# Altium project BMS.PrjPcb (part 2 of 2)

## Sheet USB protection.SchDoc
size A3; SheetNumber: 3; SheetTotal: 5
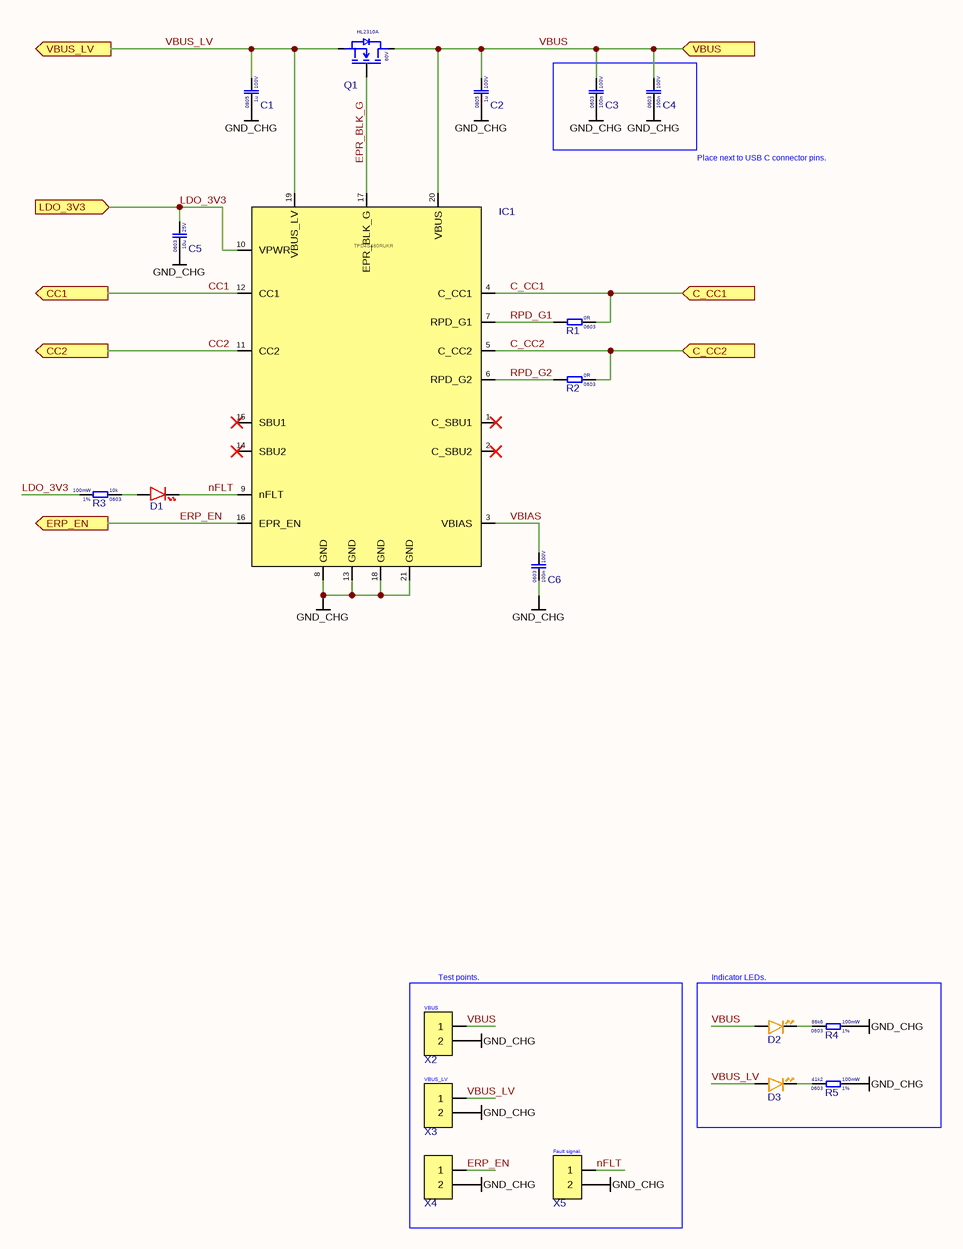
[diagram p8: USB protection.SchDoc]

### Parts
C1  Voltage Rating: 100V  Case Code (Imperial): 0805  Capacitance: 1u  [Cap_0805]  (hidden comment: CC0805KKX7R0BB105)
C2  Voltage Rating: 100V  Case Code (Imperial): 0805  Capacitance: 1u  [Cap_0805]  (hidden comment: CC0805KKX7R0BB105)
C3  Voltage Rating: 100V  Case Code (Imperial): 0603  Capacitance: 100n  [CAP 0603]  (hidden comment: CC0603KRX7R0BB104)
C4  Voltage Rating: 100V  Case Code (Imperial): 0603  Capacitance: 100n  [CAP 0603]  (hidden comment: CC0603KRX7R0BB104)
C5  Voltage Rating: 25V  Case Code (Imperial): 0603  Capacitance: 10u  [CAP 0603]  (hidden comment: CL10A106MA8NRNC)
C6  Voltage Rating: 100V  Case Code (Imperial): 0603  Capacitance: 100n  [CAP 0603]  (hidden comment: CC0603KRX7R0BB104)
D1  XL-1608SURC-06  [DIODE_0603_RED]  (value not drawn)
D2  XL-1608UOC-06  [DIODE_0603_ORANGE]  (value not drawn)
D3  XL-1608UOC-06  [DIODE_0603_ORANGE]  (value not drawn)
IC1  TPD4S480RUKR  [WQFN (20)]
Q1  Voltage: 60V  [SOT-23 GSD]  (hidden comment: HL2310A)
R1  Resistance: 0R  Case Code (Imperial): 0603  [RES_0603]  (hidden comment: 0603WAF0000T5E)
R2  Resistance: 0R  Case Code (Imperial): 0603  [RES_0603]  (hidden comment: 0603WAF0000T5E)
R3  Resistance Tolerance: 1%  Resistance: 10k  Power Rating: 100mW  Case Code (Imperial): 0603  [RES_0603]  (hidden comment: 0603WAF1002T5E)
R4  Resistance Tolerance: 1%  Resistance: 86k6  Power Rating: 100mW  Case Code (Imperial): 0603  [RES_0603]  (hidden comment: 0603WAF8662T5E)
R5  Resistance Tolerance: 1%  Resistance: 41k2  Power Rating: 100mW  Case Code (Imperial): 0603  [RES_0603]  (hidden comment: 0603WAF4122T5E)
X2  ZX-PZ1.27-1-2PZZ  [Pin header 1x2 1.27mmP THT Vertical]  (value not drawn)
X3  ZX-PZ1.27-1-2PZZ  [Pin header 1x2 1.27mmP THT Vertical]  (value not drawn)
X4  ZX-PZ1.27-1-2PZZ  [Pin header 1x2 1.27mmP THT Vertical]  (value not drawn)
X5  ZX-PZ1.27-1-2PZZ  [Pin header 1x2 1.27mmP THT Vertical]  (value not drawn)

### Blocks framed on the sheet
Test points.: X2-X5
Indicator LEDs.: D2 D3 R4 R5

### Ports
C_CC1 (in, see CHARGER[7B]), C_CC2 (in, see CHARGER[7B]), CC1 (out, see CHARGER[6B], USB PD[6C]), CC2 (out, see CHARGER[6B], USB PD[6C]), ERP_EN (out, see CHARGER[6B], USB PD[2B]), LDO_3V3 (in, see CHARGER[6C], USB PD[5C]), VBUS (in, see CHARGER[7B]), VBUS_LV (out, see CHARGER[6B], USB PD[6B])

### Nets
GND_CHG: C1.1 C2.1 C3.1 C4.1 C5.1 C6.1 IC1.8(GND) IC1.13(GND) IC1.18(GND) IC1.21(GND) R4.2 R5.2 X2.2 X3.2 X4.2 X5.2
LDO_3V3: C5.2 IC1.10(VPWR) R3.2 ; port LDO_3V3
C_CC1: IC1.4(C_CC1) R1.1 ; port C_CC1
C_CC2: IC1.5(C_CC2) R2.1 ; port C_CC2
CC1: IC1.12(CC1) ; port CC1
CC2: IC1.11(CC2) ; port CC2
EPR_BLK_G: IC1.17(EPR_BLK_G) Q1.G
ERP_EN: IC1.16(EPR_EN) X4.1 ; port ERP_EN
nFLT: D1.K IC1.9(nFLT) X5.1
RPD_G1: IC1.7(RPD_G1) R1.2
RPD_G2: IC1.6(RPD_G2) R2.2
VBIAS: C6.2 IC1.3(VBIAS)
VBUS: C2.2 C3.2 C4.2 D2.A IC1.20(VBUS) Q1.D X2.1 ; port VBUS
VBUS_LV: C1.2 D3.A IC1.19(VBUS_LV) Q1.S X3.1 ; port VBUS_LV
NetD1_A: D1.A R3.1
NetD2_K: D2.K R4.1
NetD3_K: D3.K R5.1

Not connected (* = marked no-connect by the designer): IC1 1(C_SBU1)* 2(C_SBU2)* 14(SBU2)* 15(SBU1)*

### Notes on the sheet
- Place next to USB C connector pins.
- (near X2) VBUS
- (near X3) VBUS_LV
- (near X5) Fault signal.

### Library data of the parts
C1 C2 = CC0805KKX7R0BB105: Cap 1uF 100V 0805 X7R; Manufacturer: Yageo
C3 C4 C6 = CC0603KRX7R0BB104: Cap 100nF 100V 0603 X7R; Manufacturer: YAGEO
C5 = CL10A106MA8NRNC: Cap 10uF 25V 0603 X5R; Manufacturer: Samsung
D1 = XL-1608SURC-06: LED Red 0603 25mA; Manufacturer: Xinglight
D2 D3 = XL-1608UOC-06: LED Orange 0603 20mA; Manufacturer: XINGLIGHT
IC1 = TPD4S480RUKR: USB PD protection IC; Manufacturer: Texas Instruments
Q1 = HL2310A: nMOS 60V 3A SOT-23; Manufacturer: hongjiacheng
R1 R2 = 0603WAF0000T5E: Res 0R 0603 1% 100mW 75V; Manufacturer: UNI-ROYAL
R3 = 0603WAF1002T5E: Res 10k 0603 1% 100mW 75V; Manufacturer: Uni-Royal
R4 = 0603WAF8662T5E: Res 86k6 0603 1% 100mW 75V; Manufacturer: Uni-Royal
R5 = 0603WAF4122T5E: Res 41k2 0603 1% 100mW 75V; Manufacturer: Uni-Royal
X2-X5 = ZX-PZ1.27-1-2PZZ: Pin header 1x2 1.27mmP THT Vertical; Manufacturer: Megastar

## Sheet USB PD.SchDoc
size A3; SheetNumber: 4; SheetTotal: 15
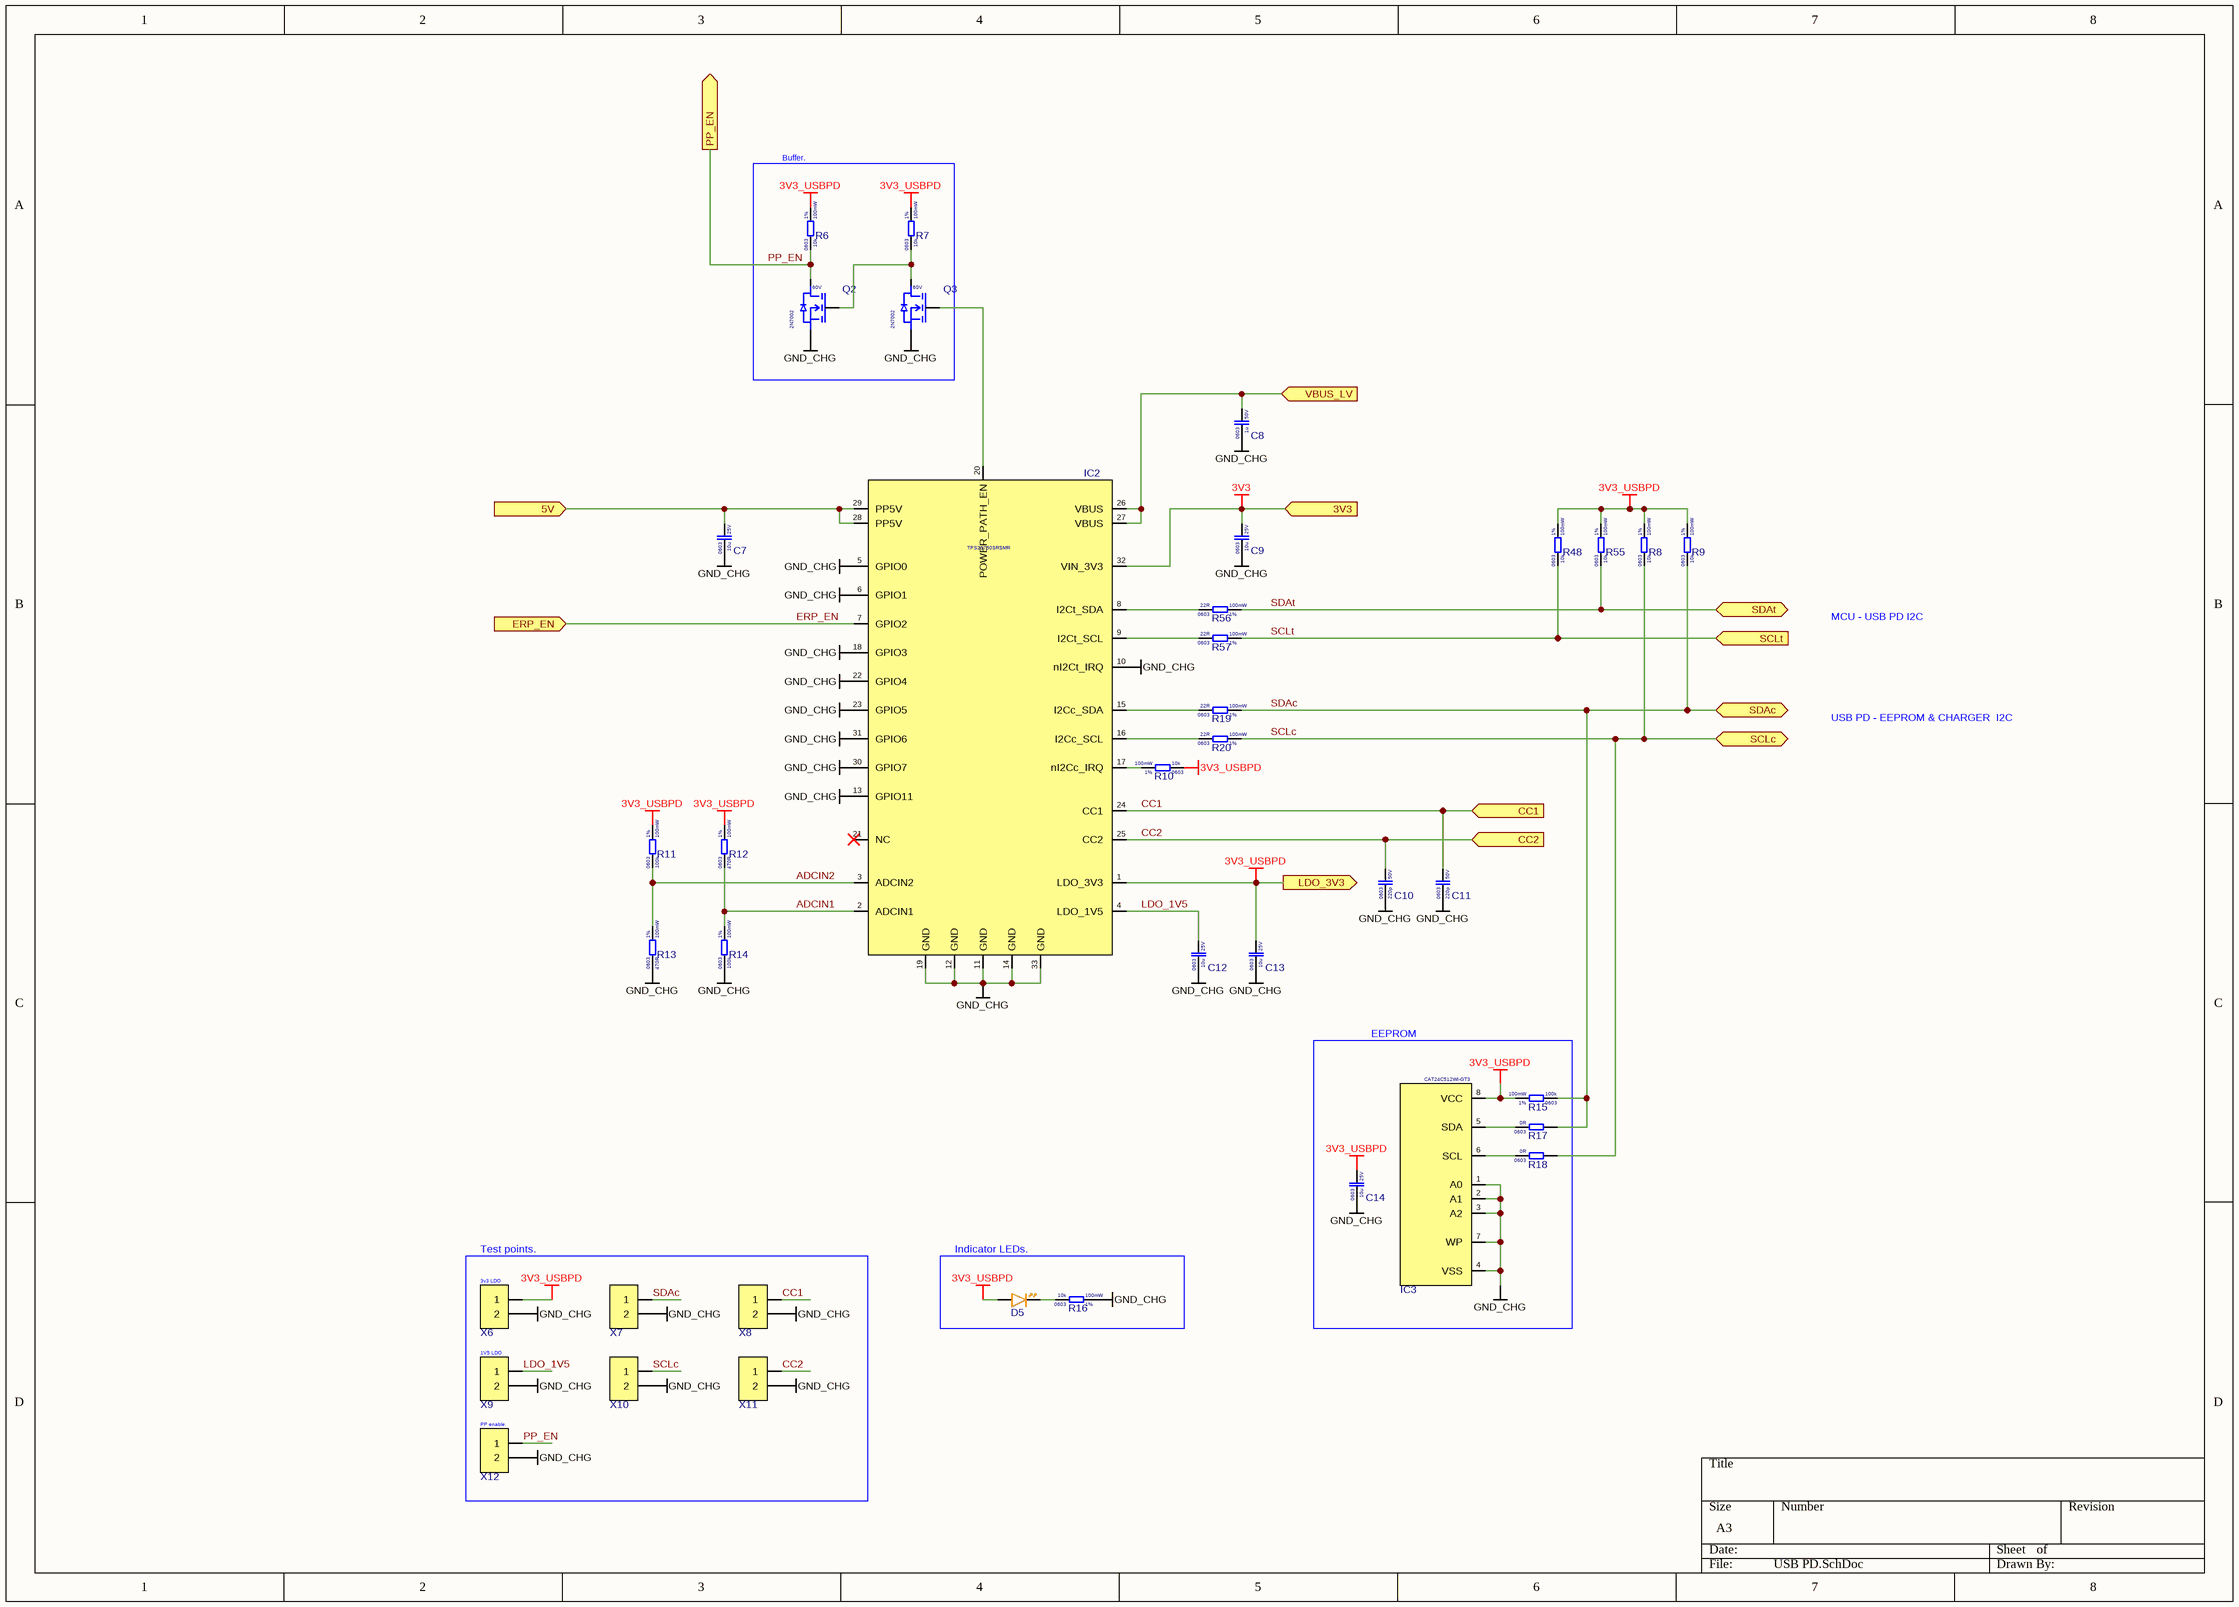
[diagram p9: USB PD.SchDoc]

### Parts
C7  Voltage Rating: 25V  Case Code (Imperial): 0603  Capacitance: 10u  [CAP 0603]  (hidden comment: CL10A106MA8NRNC)
C8  Voltage Rating: 50V  Case Code (Imperial): 0603  Capacitance: 1u  [CAP 0603]  (hidden comment: CL10A105KB8NNNC)
C9  Voltage Rating: 25V  Case Code (Imperial): 0603  Capacitance: 10u  [CAP 0603]  (hidden comment: CL10A106MA8NRNC)
C10  Voltage Rating: 50V  Case Code (Imperial): 0603  Capacitance: 220p  [CAP 0603]  (hidden comment: CL10B221KB8NNNC)
C11  Voltage Rating: 50V  Case Code (Imperial): 0603  Capacitance: 220p  [CAP 0603]  (hidden comment: CL10B221KB8NNNC)
C12  Voltage Rating: 25V  Case Code (Imperial): 0603  Capacitance: 10u  [CAP 0603]  (hidden comment: CL10A106MA8NRNC)
C13  Voltage Rating: 25V  Case Code (Imperial): 0603  Capacitance: 10u  [CAP 0603]  (hidden comment: CL10A106MA8NRNC)
C14  Voltage Rating: 25V  Case Code (Imperial): 0603  Capacitance: 10u  [CAP 0603]  (hidden comment: CL10A106MA8NRNC)
D5  XL-1608UOC-06  [DIODE_0603_ORANGE]  (value not drawn)
IC2  TPS26750SRSMR  [VQFN (32) 4x4]
IC3  CAT24C512WI-GT3  [SOIC8]
Q2  Voltage: 60V  [SOT-23 GSD]  (hidden comment: 2N7002)
Q3  Voltage: 60V  [SOT-23 GSD]  (hidden comment: 2N7002)
R6  Resistance Tolerance: 1%  Resistance: 10k  Power Rating: 100mW  Case Code (Imperial): 0603  [RES_0603]  (hidden comment: 0603WAF1002T5E)
R7  Resistance Tolerance: 1%  Resistance: 10k  Power Rating: 100mW  Case Code (Imperial): 0603  [RES_0603]  (hidden comment: 0603WAF1002T5E)
R8  Resistance Tolerance: 1%  Resistance: 10k  Power Rating: 100mW  Case Code (Imperial): 0603  [RES_0603]  (hidden comment: 0603WAF1002T5E)
R9  Resistance Tolerance: 1%  Resistance: 10k  Power Rating: 100mW  Case Code (Imperial): 0603  [RES_0603]  (hidden comment: 0603WAF1002T5E)
R10  Resistance Tolerance: 1%  Resistance: 10k  Power Rating: 100mW  Case Code (Imperial): 0603  [RES_0603]  (hidden comment: 0603WAF1002T5E)
R11  Resistance Tolerance: 1%  Resistance: 100k  Power Rating: 100mW  Case Code (Imperial): 0603  [RES_0603]  (hidden comment: 0603WAF1003T5E)
R12  Resistance Tolerance: 1%  Resistance: 470R  Power Rating: 100mW  Case Code (Imperial): 0603  [RES_0603]  (hidden comment: 0603WAF4700T5E)
R13  Resistance Tolerance: 1%  Resistance: 470R  Power Rating: 100mW  Case Code (Imperial): 0603  [RES_0603]  (hidden comment: 0603WAF4700T5E)
R14  Resistance Tolerance: 1%  Resistance: 100k  Power Rating: 100mW  Case Code (Imperial): 0603  [RES_0603]  (hidden comment: 0603WAF1003T5E)
R15  Resistance Tolerance: 1%  Resistance: 100k  Power Rating: 100mW  Case Code (Imperial): 0603  [RES_0603]  (hidden comment: 0603WAF1003T5E)
R16  Resistance Tolerance: 1%  Resistance: 10k  Power Rating: 100mW  Case Code (Imperial): 0603  [RES_0603]  (hidden comment: 0603WAF1002T5E)
R17  Resistance: 0R  Case Code (Imperial): 0603  [RES_0603]  (hidden comment: 0603WAF0000T5E)
R18  Resistance: 0R  Case Code (Imperial): 0603  [RES_0603]  (hidden comment: 0603WAF0000T5E)
R19  Resistance Tolerance: 1%  Resistance: 22R  Power Rating: 100mW  Case Code (Imperial): 0603  [RES_0603]  (hidden comment: 0603WAF220JT5E)
R20  Resistance Tolerance: 1%  Resistance: 22R  Power Rating: 100mW  Case Code (Imperial): 0603  [RES_0603]  (hidden comment: 0603WAF220JT5E)
R48  Resistance Tolerance: 1%  Resistance: 10k  Power Rating: 100mW  Case Code (Imperial): 0603  [RES_0603]  (hidden comment: 0603WAF1002T5E)
R55  Resistance Tolerance: 1%  Resistance: 10k  Power Rating: 100mW  Case Code (Imperial): 0603  [RES_0603]  (hidden comment: 0603WAF1002T5E)
R56  Resistance Tolerance: 1%  Resistance: 22R  Power Rating: 100mW  Case Code (Imperial): 0603  [RES_0603]  (hidden comment: 0603WAF220JT5E)
R57  Resistance Tolerance: 1%  Resistance: 22R  Power Rating: 100mW  Case Code (Imperial): 0603  [RES_0603]  (hidden comment: 0603WAF220JT5E)
X6  ZX-PZ1.27-1-2PZZ  [Pin header 1x2 1.27mmP THT Vertical]  (value not drawn)
X7  ZX-PZ1.27-1-2PZZ  [Pin header 1x2 1.27mmP THT Vertical]  (value not drawn)
X8  ZX-PZ1.27-1-2PZZ  [Pin header 1x2 1.27mmP THT Vertical]  (value not drawn)
X9  ZX-PZ1.27-1-2PZZ  [Pin header 1x2 1.27mmP THT Vertical]  (value not drawn)
X10  ZX-PZ1.27-1-2PZZ  [Pin header 1x2 1.27mmP THT Vertical]  (value not drawn)
X11  ZX-PZ1.27-1-2PZZ  [Pin header 1x2 1.27mmP THT Vertical]  (value not drawn)
X12  ZX-PZ1.27-1-2PZZ  [Pin header 1x2 1.27mmP THT Vertical]  (value not drawn)

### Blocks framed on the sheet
Buffer.: Q2 Q3 R6 R7
EEPROM: C14 IC3 R15 R17 R18
Test points.: X6-X12
Indicator LEDs.: D5 R16

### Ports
3V3 (in, see CHARGER[5C], Power distribution[6C]), 5V (in, see CHARGER[5B], Power distribution[6C]), CC1 (in, see CHARGER[6B], USB protection[3B]), CC2 (in, see CHARGER[6B], USB protection[3B]), ERP_EN (in, see CHARGER[6B], USB protection[3C]), LDO_3V3 (out, see CHARGER[6C], USB protection[3B]), PP_EN (out, see CHARGER[5B], Power path switch[5C]), SCLc (bidir, see CHARGER[5B], CHARGER[1D]), SCLt (in, see CHARGER[5B], CHARGER[1D]), SDAc (bidir, see CHARGER[5B], CHARGER[1D]), SDAt (bidir, see CHARGER[5B], CHARGER[1D]), VBUS_LV (in, see CHARGER[6B], USB protection[3A])

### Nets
3V3: C9.2 IC2.32(VIN_3V3) ; port 3V3
3V3_USBPD: C13.2 C14.2 D5.A IC2.1(LDO_3V3) IC3.8(VCC) R6.2 R7.2 R8.2 R9.2 R10.1 R11.2 R12.2 R15.2 R48.2 R55.2 X6.1 ; port LDO_3V3  [project net LDO_3V3]
5V: C7.2 IC2.28(PP5V) IC2.29(PP5V) ; port 5V
GND_CHG: C7.1 C8.1 C9.1 C10.1 C11.1 C12.1 C13.1 C14.1 IC2.5(GPIO0) IC2.6(GPIO1) IC2.10(nI2Ct_IRQ) IC2.11(GND) IC2.12(GND) IC2.13(GPIO11) IC2.14(GND) IC2.18(GPIO3) IC2.19(GND) IC2.22(GPIO4) IC2.23(GPIO5) IC2.30(GPIO7) IC2.31(GPIO6) IC2.33(GND) IC3.1(A0) IC3.2(A1) IC3.3(A2) IC3.4(VSS) IC3.7(WP) Q2.S Q3.S R13.1 R14.1 R16.2 X6.2 X7.2 X8.2 X9.2 X10.2 X11.2 X12.2
ADCIN1: IC2.2(ADCIN1) R12.1 R14.2
ADCIN2: IC2.3(ADCIN2) R11.1 R13.2
CC1: C11.2 IC2.24(CC1) X8.1 ; port CC1
CC2: C10.2 IC2.25(CC2) X11.1 ; port CC2
ERP_EN: IC2.7(GPIO2) ; port ERP_EN
LDO_1V5: C12.2 IC2.4(LDO_1V5) X9.1
PP_EN: Q2.D R6.1 X12.1 ; port PP_EN
SCLc: R8.1 R18.2 R20.2 X10.1 ; port SCLc  [project net SCL]
SCLt: R48.1 R57.2 ; port SCLt
SDAc: R9.1 R15.1 R17.2 R19.2 X7.1 ; port SDAc  [project net SDA]
SDAt: R55.1 R56.2 ; port SDAt
VBUS_LV: C8.2 IC2.26(VBUS) IC2.27(VBUS) ; port VBUS_LV
NetD5_K: D5.K R16.1
NetIC2_8: IC2.8(I2Ct_SDA) R56.1
NetIC2_9: IC2.9(I2Ct_SCL) R57.1
NetIC2_15: IC2.15(I2Cc_SDA) R19.1
NetIC2_16: IC2.16(I2Cc_SCL) R20.1
NetIC2_17: IC2.17(nI2Cc_IRQ) R10.2
NetIC2_20: IC2.20(POWER_PATH_EN) Q3.G
NetIC3_5: IC3.5(SDA) R17.1
NetIC3_6: IC3.6(SCL) R18.1
NetQ2_G: Q2.G Q3.D R7.1

Not connected (* = marked no-connect by the designer): IC2 21(NC)*

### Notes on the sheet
- MCU - USB PD I2C
- USB PD - EEPROM & CHARGER  I2C
- (near X6) 3v3 LDO
- (near X9) 1V5 LDO
- (near X12) PP enable.

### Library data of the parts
C7 C9 C12-C14 = CL10A106MA8NRNC: as C5 on sheet USB protection
C8 = CL10A105KB8NNNC: Cap 1uF 50V 0603 X5R; Manufacturer: Samsung
C10 C11 = CL10B221KB8NNNC: Cap 220pF 50V 0603 X7R; Manufacturer: Samsung
D5 = XL-1608UOC-06: as D2 on sheet USB protection
IC2 = TPS26750SRSMR: USB PD IC EPR 240W; Manufacturer: Texas Instruments
IC3 = CAT24C512WI-GT3: EEPROM SOIC-8; Manufacturer: OnSemi
Q2 Q3 = 2N7002: nMOS 60V 115mA SOT-23; Manufacturer: Jiangsu Changjing Electronics Technology Co., Ltd.
R6-R10 R16 R48 R55 = 0603WAF1002T5E: as R3 on sheet USB protection
R11 R14 R15 = 0603WAF1003T5E: Res 100k 0603 1% 100mW 75V; Manufacturer: Uni-Royal
R12 R13 = 0603WAF4700T5E: Res 470R 0603 1% 100mW 75V; Manufacturer: Uni-Royal
R17 R18 = 0603WAF0000T5E: as R1 on sheet USB protection
R19 R20 R56 R57 = 0603WAF220JT5E: Res 22R 0603 1% 100mW 75V; Manufacturer: Uni-Royal
X6-X12 = ZX-PZ1.27-1-2PZZ: as X2 on sheet USB protection

## Sheet Power path switch.SchDoc
size A3; SheetNumber: 5; SheetTotal: 7
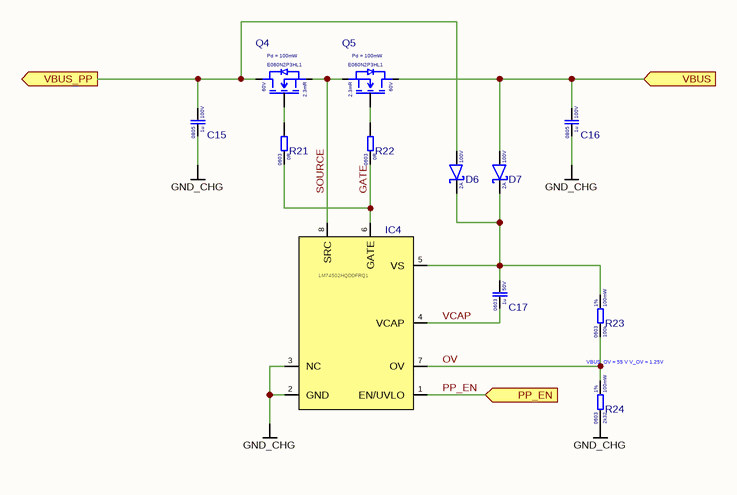
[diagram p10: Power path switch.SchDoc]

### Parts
C15  Voltage Rating: 100V  Case Code (Imperial): 0805  Capacitance: 1u  [Cap_0805]  (hidden comment: CC0805KKX7R0BB105)
C16  Voltage Rating: 100V  Case Code (Imperial): 0805  Capacitance: 1u  [Cap_0805]  (hidden comment: CC0805KKX7R0BB105)
C17  Voltage Rating: 50V  Case Code (Imperial): 0603  Capacitance: 1u  [CAP 0603]  (hidden comment: CL10A105KB8NNNC)
D6  Forward Current: 2A  Reverse Voltage: 100V  [SMAF]  (hidden comment: SS210F)
D7  Forward Current: 2A  Reverse Voltage: 100V  [SMAF]  (hidden comment: SS210F)
IC4  LM74502HQDDFRQ1  [SOT-23-8]
Q4  Pd = 100mW  Rds: 2.3mR  Voltage: 60V  [DFN-8 (5x6)]
Q5  Pd = 100mW  Rds: 2.3mR  Voltage: 60V  [DFN-8 (5x6)]
R21  Resistance: 0R  Case Code (Imperial): 0603  [RES_0603]  (hidden comment: 0603WAF0000T5E)
R22  Resistance: 0R  Case Code (Imperial): 0603  [RES_0603]  (hidden comment: 0603WAF0000T5E)
R23  Resistance Tolerance: 1%  Resistance: 100k  Power Rating: 100mW  Case Code (Imperial): 0603  [RES_0603]  (hidden comment: 0603WAF1003T5E)
R24  Resistance Tolerance: 1%  Resistance: 2k32  Power Rating: 100mW  Case Code (Imperial): 0603  [RES_0603]  (hidden comment: FRC0603F2321TS)

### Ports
PP_EN (in, see CHARGER[5A], USB PD[3A]), VBUS (in, see CHARGER[6A], USB protection[5A]), VBUS_PP (out, see CHARGER[5A])

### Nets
GND_CHG: C15.1 C16.1 IC4.2(GND) IC4.3(NC) R24.1
GATE: IC4.6(GATE) R21.1 R22.1
OV: IC4.7(OV) R23.1 R24.2
PP_EN: IC4.1(EN/UVLO) ; port PP_EN
SOURCE: IC4.8(SRC) Q4.S Q5.S
V_CHG_IN: C15.2 D6.A Q4.D ; port VBUS_PP
VBUS: C16.2 D7.A Q5.D ; port VBUS
VCAP: C17.1 IC4.4(VCAP)
NetC17_2: C17.2 D6.K D7.K IC4.5(VS) R23.2
NetQ4_G: Q4.G R21.2
NetQ5_G: Q5.G R22.2

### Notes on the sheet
- VBUS_OV = 55 V V_OV = 1.25V

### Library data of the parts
C15 C16 = CC0805KKX7R0BB105: as C1 on sheet USB protection
C17 = CL10A105KB8NNNC: as C8 on sheet USB PD
D6 D7 = SS210F: Schottky 100V 2A 850mVf SMAF; Manufacturer: GOODWORK
IC4 = LM74502HQDDFRQ1: High-side switch controller IC 3.2~65V Reverse polarity protection; Manufacturer: Texas Instruments
Q4 Q5 = E060N2P3HL1: Nmos 60V 180A 2.3mR PDFN5x6-8; Manufacturer: Existar
R21 R22 = 0603WAF0000T5E: as R1 on sheet USB protection
R23 = 0603WAF1003T5E: as R11 on sheet USB PD
R24 = FRC0603F2321TS: Res 2k32 0603 1% 100mW 75V; Manufacturer: Uni-Royal

## Sheet Charger BQ25756.SchDoc
size A3; SheetNumber: 6; SheetTotal: 15
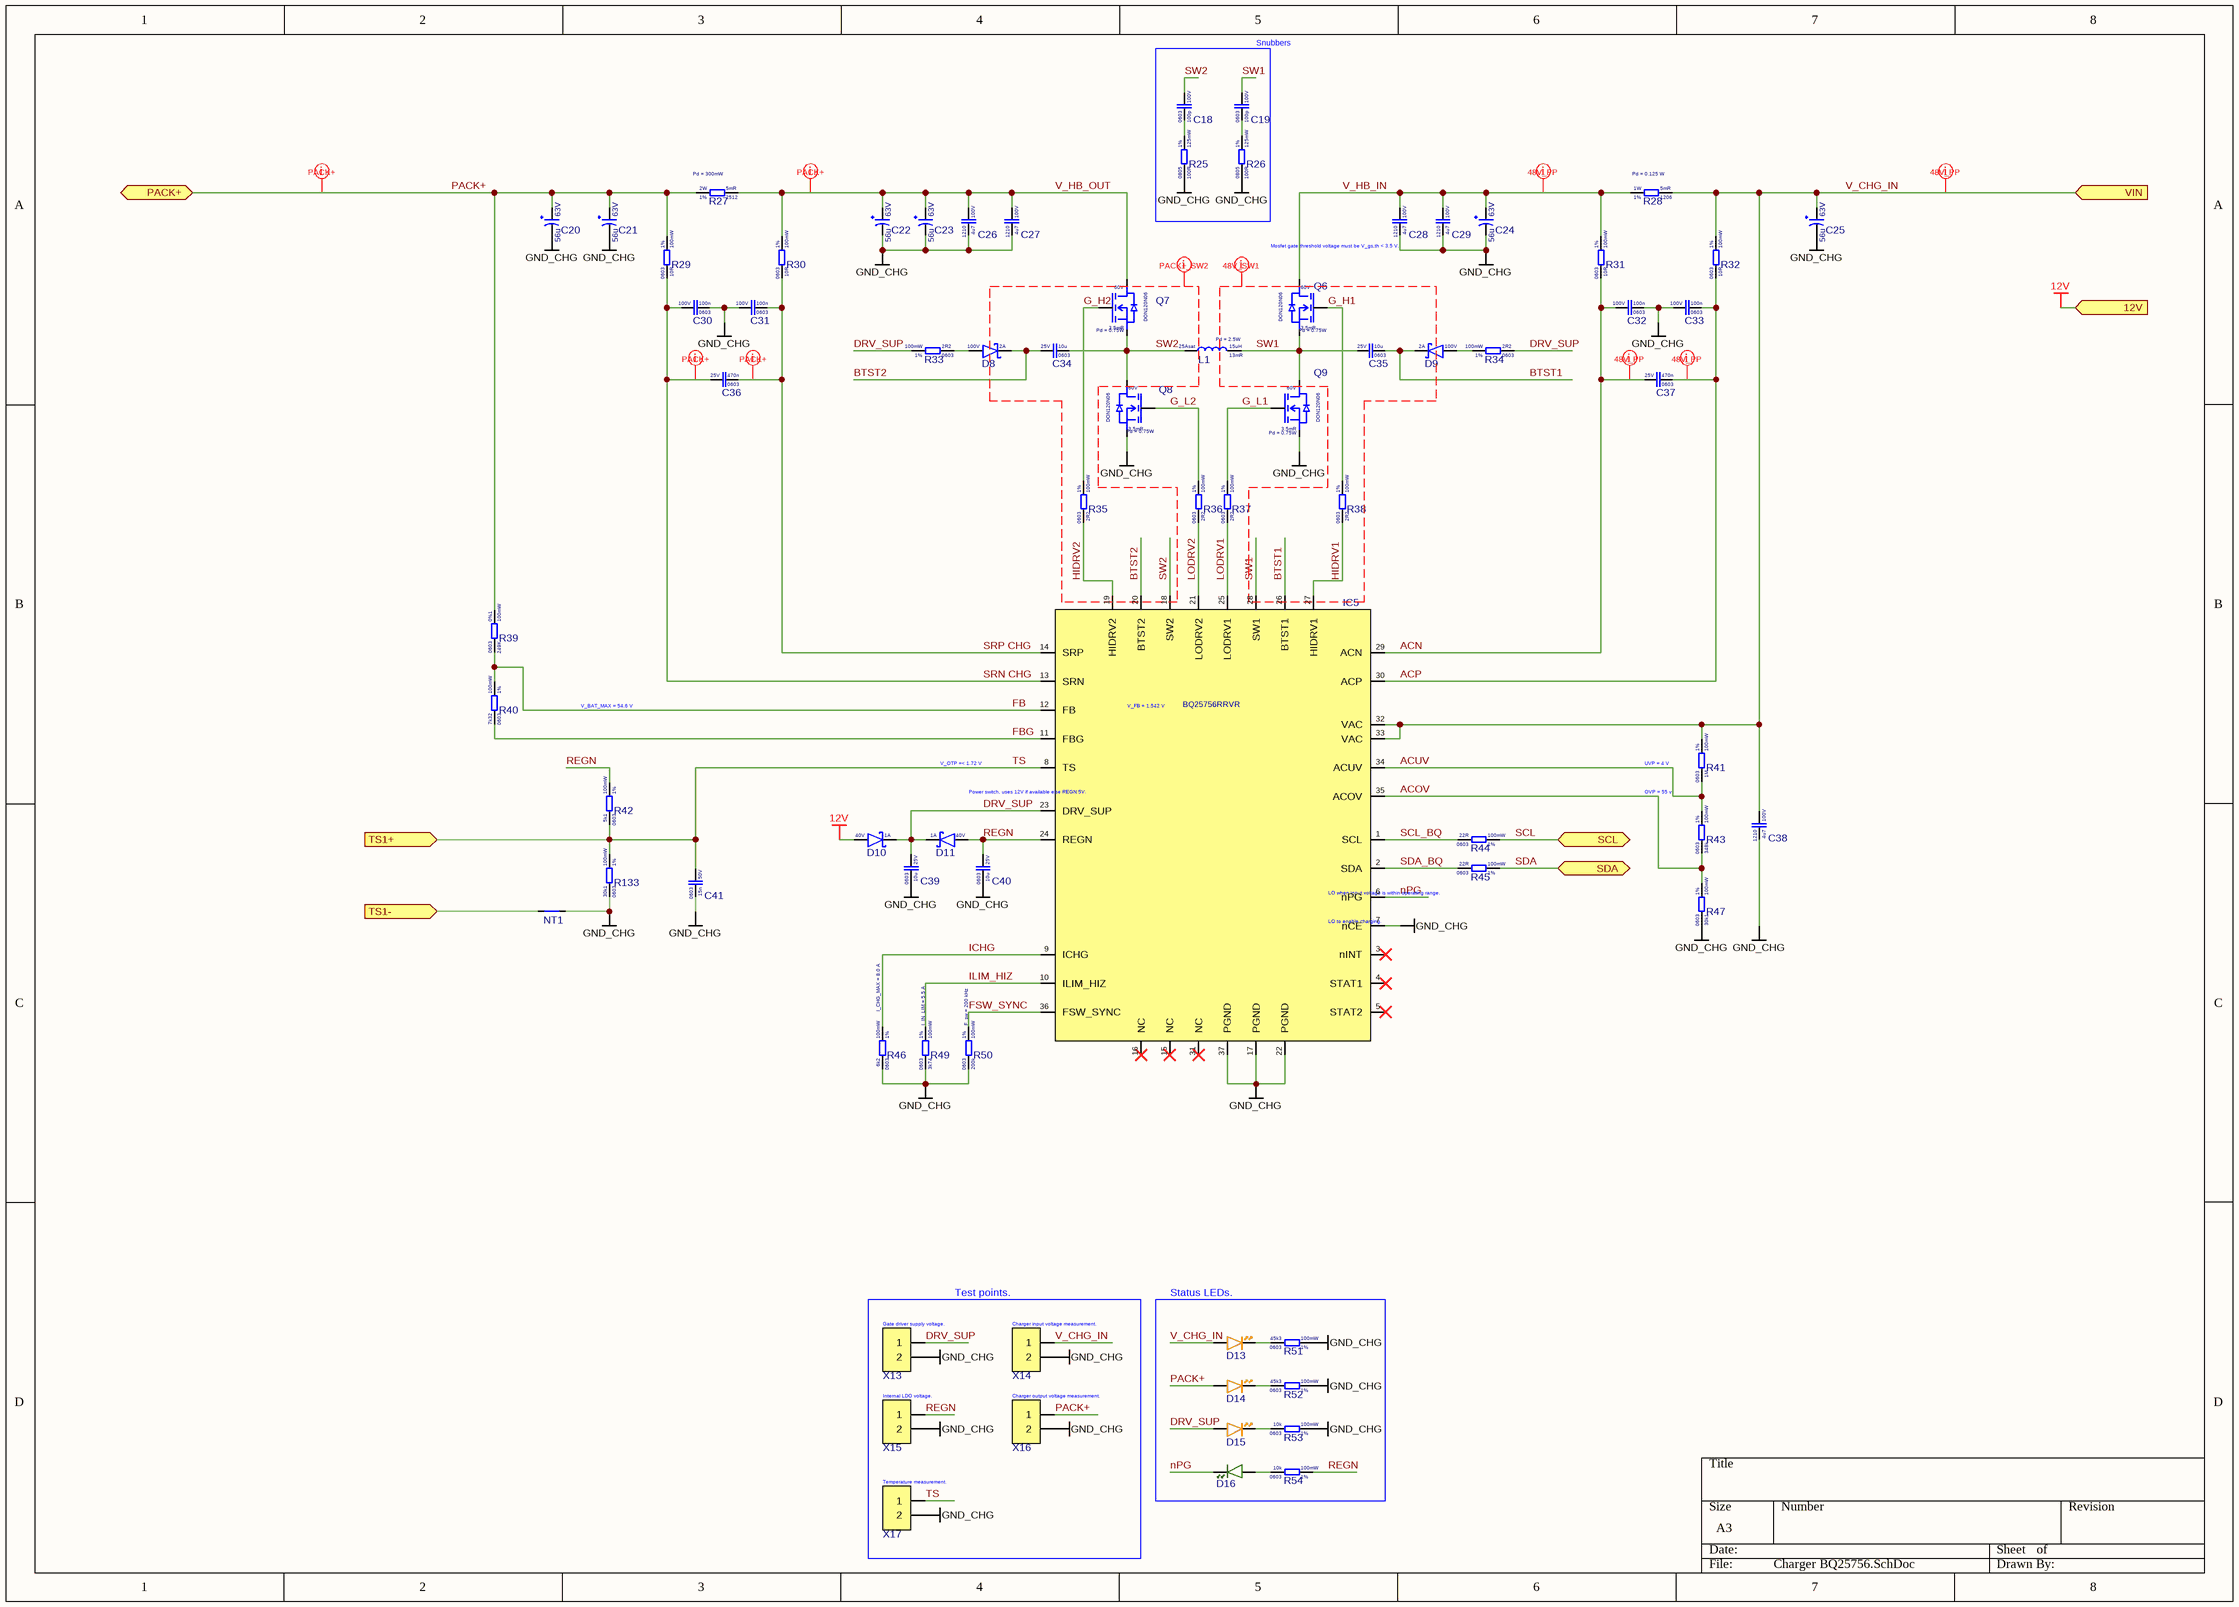
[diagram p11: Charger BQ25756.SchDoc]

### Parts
C18  Voltage Rating: 100V  Case Code (Imperial): 0603  Capacitance: 100p  [CAP 0603]  (hidden comment: CC0603JRNPO0BN101)
C19  Voltage Rating: 100V  Case Code (Imperial): 0603  Capacitance: 100p  [CAP 0603]  (hidden comment: CC0603JRNPO0BN101)
C20  Voltage Rating: 63V  Capacitance: 56u  [CAP_SMD_10X10.2]  (hidden comment: EEHZA1J560P)
C21  Voltage Rating: 63V  Capacitance: 56u  [CAP_SMD_10X10.2]  (hidden comment: EEHZA1J560P)
C22  Voltage Rating: 63V  Capacitance: 56u  [CAP_SMD_10X10.2]  (hidden comment: EEHZA1J560P)
C23  Voltage Rating: 63V  Capacitance: 56u  [CAP_SMD_10X10.2]  (hidden comment: EEHZA1J560P)
C24  Voltage Rating: 63V  Capacitance: 56u  [CAP_SMD_10X10.2]  (hidden comment: EEHZA1J560P)
C25  Voltage Rating: 63V  Capacitance: 56u  [CAP_SMD_10X10.2]  (hidden comment: EEHZA1J560P)
C26  Voltage Rating: 100V  Case Code (Imperial): 1210  Capacitance: 4u7  [CAP_1210]  (hidden comment: HMK325C7475KN-TE)
C27  Voltage Rating: 100V  Case Code (Imperial): 1210  Capacitance: 4u7  [CAP_1210]  (hidden comment: HMK325C7475KN-TE)
C28  Voltage Rating: 100V  Case Code (Imperial): 1210  Capacitance: 4u7  [CAP_1210]  (hidden comment: HMK325C7475KN-TE)
C29  Voltage Rating: 100V  Case Code (Imperial): 1210  Capacitance: 4u7  [CAP_1210]  (hidden comment: HMK325C7475KN-TE)
C30  Voltage Rating: 100V  Case Code (Imperial): 0603  Capacitance: 100n  [CAP 0603]  (hidden comment: CC0603KRX7R0BB104)
C31  Voltage Rating: 100V  Case Code (Imperial): 0603  Capacitance: 100n  [CAP 0603]  (hidden comment: CC0603KRX7R0BB104)
C32  Voltage Rating: 100V  Case Code (Imperial): 0603  Capacitance: 100n  [CAP 0603]  (hidden comment: CC0603KRX7R0BB104)
C33  Voltage Rating: 100V  Case Code (Imperial): 0603  Capacitance: 100n  [CAP 0603]  (hidden comment: CC0603KRX7R0BB104)
C34  Voltage Rating: 25V  Case Code (Imperial): 0603  Capacitance: 10u  [CAP 0603]  (hidden comment: CL10A106MA8NRNC)
C35  Voltage Rating: 25V  Case Code (Imperial): 0603  Capacitance: 10u  [CAP 0603]  (hidden comment: CL10A106MA8NRNC)
C36  Voltage Rating: 25V  Case Code (Imperial): 0603  Capacitance: 470n  [CAP 0603]  (hidden comment: CL10B474KA8NNNC)
C37  Voltage Rating: 25V  Case Code (Imperial): 0603  Capacitance: 470n  [CAP 0603]  (hidden comment: CL10B474KA8NNNC)
C38  Voltage Rating: 100V  Case Code (Imperial): 1210  Capacitance: 4u7  [CAP_1210]  (hidden comment: HMK325C7475KN-TE)
C39  Voltage Rating: 25V  Case Code (Imperial): 0603  Capacitance: 10u  [CAP 0603]  (hidden comment: CL10A106MA8NRNC)
C40  Voltage Rating: 25V  Case Code (Imperial): 0603  Capacitance: 10u  [CAP 0603]  (hidden comment: CL10A106MA8NRNC)
C41  Voltage Rating: 50V  Case Code (Imperial): 0603  Capacitance: 15n  [CAP 0603]  (hidden comment: CC0603KRX7R9BB153)
D8  Forward Current: 2A  Reverse Voltage: 100V  [SMAF]  (hidden comment: SS210F)
D9  Forward Current: 2A  Reverse Voltage: 100V  [SMAF]  (hidden comment: SS210F)
D10  Forward Current: 1A  Reverse Voltage: 40V  [SOD-323]  (hidden comment: 1N5819WS)
D11  Forward Current: 1A  Reverse Voltage: 40V  [SOD-323]  (hidden comment: 1N5819WS)
D13  XL-1608UOC-06  [DIODE_0603_ORANGE]  (value not drawn)
D14  XL-1608UOC-06  [DIODE_0603_ORANGE]  (value not drawn)
D15  XL-1608UOC-06  [DIODE_0603_ORANGE]  (value not drawn)
D16  PSC-1608U52GC-G4  [DIODE_0603_GREEN]  (value not drawn)
IC5  BQ25756RRVR  [VQFN-36(5x6)]
L1  Pd = 2.5W  Resistance: 13mR  Saturation current: 25Asat  Inductance: 15uH  [IND 17.5x17.15x7.0]
NT1  NT  [NETTIE_0.3MM]  (value not drawn)  (net tie, no BOM)
Q6  Pd = 0.75W  Rds: 3.5mR  Voltage: 60V  [DFN-8 (5x6)]
Q7  Pd = 0.75W  Rds: 3.5mR  Voltage: 60V  [DFN-8 (5x6)]
Q8  Pd = 0.75W  Rds: 3.5mR  Voltage: 60V  [DFN-8 (5x6)]
Q9  Pd = 0.75W  Rds: 3.5mR  Voltage: 60V  [DFN-8 (5x6)]
R25  Resistance Tolerance: 1%  Resistance: 100R  Power Rating: 125mW  Case Code (Imperial): 0805  [Res_0805]  (hidden comment: 0805W8F1000T5E)
R26  Resistance Tolerance: 1%  Resistance: 100R  Power Rating: 125mW  Case Code (Imperial): 0805  [Res_0805]  (hidden comment: 0805W8F1000T5E)
R27  Pd = 300mW  Resistance Tolerance: 1%  Resistance: 5mR  Power Rating: 2W  Case Code (Imperial): 2512  [RES_2512]
R28  Pd = 0.125 W  Resistance Tolerance: 1%  Resistance: 5mR  Power Rating: 1W  Case Code (Imperial): 1206  [RES_1206]
R29  Resistance Tolerance: 1%  Resistance: 10R  Power Rating: 100mW  Case Code (Imperial): 0603  [RES_0603]  (hidden comment: 0603WAF100JT5E)
R30  Resistance Tolerance: 1%  Resistance: 10R  Power Rating: 100mW  Case Code (Imperial): 0603  [RES_0603]  (hidden comment: 0603WAF100JT5E)
R31  Resistance Tolerance: 1%  Resistance: 10R  Power Rating: 100mW  Case Code (Imperial): 0603  [RES_0603]  (hidden comment: 0603WAF100JT5E)
R32  Resistance Tolerance: 1%  Resistance: 10R  Power Rating: 100mW  Case Code (Imperial): 0603  [RES_0603]  (hidden comment: 0603WAF100JT5E)
R33  Resistance Tolerance: 1%  Resistance: 2R2  Power Rating: 100mW  Case Code (Imperial): 0603  [RES_0603]  (hidden comment: 0603WAF220KT5E)
R34  Resistance Tolerance: 1%  Resistance: 2R2  Power Rating: 100mW  Case Code (Imperial): 0603  [RES_0603]  (hidden comment: 0603WAF220KT5E)
R35  Resistance Tolerance: 1%  Resistance: 2R2  Power Rating: 100mW  Case Code (Imperial): 0603  [RES_0603]  (hidden comment: 0603WAF220KT5E)
R36  Resistance Tolerance: 1%  Resistance: 2R2  Power Rating: 100mW  Case Code (Imperial): 0603  [RES_0603]  (hidden comment: 0603WAF220KT5E)
R37  Resistance Tolerance: 1%  Resistance: 2R2  Power Rating: 100mW  Case Code (Imperial): 0603  [RES_0603]  (hidden comment: 0603WAF220KT5E)
R38  Resistance Tolerance: 1%  Resistance: 2R2  Power Rating: 100mW  Case Code (Imperial): 0603  [RES_0603]  (hidden comment: 0603WAF220KT5E)
R39  Resistance Tolerance: 0%1  Resistance: 249K  Power Rating: 100mW  Case Code (Imperial): 0603  [RES_0603]  (hidden comment: RT0603BRD07249KL)
R40  Resistance Tolerance: 1%  Resistance: 7k32  Power Rating: 100mW  Case Code (Imperial): 0603  [RES_0603]  (hidden comment: FRC0603F7321TS)
R41  Resistance Tolerance: 1%  Resistance: 1M  Power Rating: 100mW  Case Code (Imperial): 0603  [RES_0603]  (hidden comment: 0603WAF1004T5E)
R42  Resistance Tolerance: 1%  Resistance: 5k1  Power Rating: 100mW  Case Code (Imperial): 0603  [RES_0603]  (hidden comment: 0603WAF5101T5E)
R43  Resistance Tolerance: 1%  Resistance: 348k  Power Rating: 100mW  Case Code (Imperial): 0603  [RES_0603]  (hidden comment: 0603WAF3483T5E)
R44  Resistance Tolerance: 1%  Resistance: 22R  Power Rating: 100mW  Case Code (Imperial): 0603  [RES_0603]  (hidden comment: 0603WAF220JT5E)
R45  Resistance Tolerance: 1%  Resistance: 22R  Power Rating: 100mW  Case Code (Imperial): 0603  [RES_0603]  (hidden comment: 0603WAF220JT5E)
R46  I_CHG_MAX = 8.0 A  Resistance Tolerance: 1%  Resistance: 6k2  Power Rating: 100mW  Case Code (Imperial): 0603  [RES_0603]
R47  Resistance Tolerance: 1%  Resistance: 30k1  Power Rating: 100mW  Case Code (Imperial): 0603  [RES_0603]  (hidden comment: 0603WAF3012T5E)
R49  I_IN_LIM = 5.5 A  Resistance Tolerance: 1%  Resistance: 3k74  Power Rating: 100mW  Case Code (Imperial): 0603  [RES_0603]
R50  F_sw = 200 kHz  Resistance Tolerance: 1%  Resistance: 200k  Power Rating: 100mW  Case Code (Imperial): 0603  [RES_0603]
R51  Resistance Tolerance: 1%  Resistance: 45k3  Power Rating: 100mW  Case Code (Imperial): 0603  [RES_0603]  (hidden comment: 0603WAF4532T5E)
R52  Resistance Tolerance: 1%  Resistance: 45k3  Power Rating: 100mW  Case Code (Imperial): 0603  [RES_0603]  (hidden comment: 0603WAF4532T5E)
R53  Resistance Tolerance: 1%  Resistance: 10k  Power Rating: 100mW  Case Code (Imperial): 0603  [RES_0603]  (hidden comment: 0603WAF1002T5E)
R54  Resistance Tolerance: 1%  Resistance: 10k  Power Rating: 100mW  Case Code (Imperial): 0603  [RES_0603]  (hidden comment: 0603WAF1002T5E)
R133  Resistance Tolerance: 1%  Resistance: 30k1  Power Rating: 100mW  Case Code (Imperial): 0603  [RES_0603]  (hidden comment: 0603WAF3012T5E)
X13  ZX-PZ1.27-1-2PZZ  [Pin header 1x2 1.27mmP THT Vertical]  (value not drawn)
X14  ZX-PZ1.27-1-2PZZ  [Pin header 1x2 1.27mmP THT Vertical]  (value not drawn)
X15  ZX-PZ1.27-1-2PZZ  [Pin header 1x2 1.27mmP THT Vertical]  (value not drawn)
X16  ZX-PZ1.27-1-2PZZ  [Pin header 1x2 1.27mmP THT Vertical]  (value not drawn)
X17  ZX-PZ1.27-1-2PZZ  [Pin header 1x2 1.27mmP THT Vertical]  (value not drawn)

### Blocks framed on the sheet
Snubbers: C18 C19 R25 R26
Test points.: X13-X17
Status LEDs.: D13-D16 R51-R54

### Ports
12V (in, see CHARGER[4B], Power distribution[6B]), PACK+ (bidir, see CHARGER[3B], BMS[8A], BQ76952 BMS[8A], CHARGER[1B], Power distribution[3A]), SCL (bidir, see CHARGER[4B]), SDA (bidir, see CHARGER[4B]), TS1+ (in, see CHARGER[3B], CHARGER[1B], ESD battery side[5C]), TS1- (in, see CHARGER[3B], CHARGER[1B], ESD battery side[5C]), VIN (in, see CHARGER[4B])

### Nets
12V: D10.A ; port 12V
GND_CHG: C20.- C21.- C22.- C23.- C24.- C25.- C26.1 C27.1 C28.1 C29.1 C30.1 C31.2 C32.1 C33.2 C38.1 C39.1 C40.1 C41.1 IC5.7(nCE) IC5.17(PGND) IC5.22(PGND) IC5.37(PGND) NT1.2 Q8.S Q9.S R25.1 R26.1 R46.1 R47.1 R49.1 R50.1 R51.2 R52.2 R53.2 R133.1 X13.2 X14.2 X15.2 X16.2 X17.2
ACN: C32.2 C37.2 IC5.29(ACN) R31.1
ACOV: IC5.35(ACOV) R43.1 R47.2
ACP: C33.1 C37.1 IC5.30(ACP) R32.1
ACUV: IC5.34(ACUV) R41.1 R43.2
BTST1: C35.1 D9.K IC5.26(BTST1)
BTST2: C34.2 D8.K IC5.20(BTST2)
DRV_SUP: C39.2 D10.K D11.K D15.A IC5.23(DRV_SUP) R33.2 R34.1 X13.1
FB: IC5.12(FB) R39.1 R40.2
FBG: IC5.11(FBG) R40.1
FSW_SYNC: IC5.36(FSW_SYNC) R50.2
G_H1: Q6.G R38.2
G_H2: Q7.G R35.2
G_L1: Q9.G R37.2
G_L2: Q8.G R36.2
HIDRV1: IC5.27(HIDRV1) R38.1
HIDRV2: IC5.19(HIDRV2) R35.1
ICHG: IC5.9(ICHG) R46.2
ILIM_HIZ: IC5.10(ILIM_HIZ) R49.2
LODRV1: IC5.25(LODRV1) R37.1
LODRV2: IC5.21(LODRV2) R36.1
nPG: D16.K IC5.6(nPG)
PACK+: C20.+ C21.+ D14.A R27.2 R29.2 R39.2 X16.1 ; port PACK+
REGN: C40.2 D11.A IC5.24(REGN) R42.2 R54.2 X15.1
SCL: R44.2 ; port SCL
SCL_BQ: IC5.1(SCL) R44.1
SDA: R45.2 ; port SDA
SDA_BQ: IC5.2(SDA) R45.1
SRN CHG: C30.2 C36.2 IC5.13(SRN) R29.1
SRP CHG: C31.1 C36.1 IC5.14(SRP) R30.1
SW1: C19.2 C35.2 IC5.28(SW1) L1.1 Q6.S Q9.D
SW2: C18.2 C34.1 IC5.18(SW2) L1.2 Q7.S Q8.D
TS: C41.2 IC5.8(TS) R42.1 R133.2 X17.1 ; port TS1+
V_CHG_IN: C25.+ C38.2 D13.A IC5.32(VAC) IC5.33(VAC) R28.1 R32.2 R41.2 X14.1 ; port VIN
V_HB_IN: C24.+ C28.2 C29.2 Q6.D R28.2 R31.2
V_HB_OUT: C22.+ C23.+ C26.2 C27.2 Q7.D R27.1 R30.2
NetC18_1: C18.1 R25.2
NetC19_1: C19.1 R26.2
NetD8_A: D8.A R33.1
NetD9_A: D9.A R34.2
NetD13_K: D13.K R51.1
NetD14_K: D14.K R52.1
NetD15_K: D15.K R53.1
NetD16_A: D16.A R54.1
NetD40_A: NT1.1 ; port TS1-

Not connected (* = marked no-connect by the designer): IC5 3(nINT)* 4(STAT1)* 5(STAT2)* 15(NC)* 16(NC)* 31(NC)*

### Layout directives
net class 48V_PP: ACN, ACP, V_CHG_IN, V_HB_IN
net class PACK+: PACK+, SRN CHG, SRP CHG, V_HB_OUT
net class 48V_SW1: BTST1, G_H1, G_L1, GND_CHG, HIDRV1, LODRV1, SW1
net class PACK+_SW2: BTST2, G_H2, G_L2, GND_CHG, HIDRV2, LODRV2, SW2

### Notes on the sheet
- Mosfet gate threshold voltage must be V_gs,th < 3.5 V.
- (near R40) V_BAT_MAX = 54.6 V
- V_OTP =< 1.72 V
- (near IC5) V_FB = 1.542 V
- UVP = 4 V
- Power switch, uses 12V if available else REGN 5V.
- OVP = 55 v
- (near IC5) LO when input voltage is within operating range.
- (near IC5) LO to enable charging.
- (near X13) Gate driver supply voltage.
- (near X14) Charger input voltage measurement.
- (near X15) Internal LDO voltage.
- (near X16) Charger output voltage measurement.
- (near X17) Temperature measurement.

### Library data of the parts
C18 C19 = CC0603JRNPO0BN101: Cap 100pF 100V 0603 NP0; Manufacturer: Yageo; Manufacturer Part Number: CC0603KRX7R9BB104
C20-C25 = EEHZA1J560P: Cap AL-EL 56uF 63V 30mR 1.8Ar SMD 10x10.2mm; Manufacturer: Panasonic
C26-C29 C38 = HMK325C7475KN-TE: Cap 4.7uF 100V 1210 X7R; Manufacturer: Taiyo Yuden
C30-C33 = CC0603KRX7R0BB104: as C3 on sheet USB protection
C34 C35 C39 C40 = CL10A106MA8NRNC: as C5 on sheet USB protection
C36 C37 = CL10B474KA8NNNC: Cap 470nF 25V 0603 X7R; Manufacturer: Samsung
C41 = CC0603KRX7R9BB153: Cap 15nF 50V 0603 X7R; Manufacturer: Yageo; Manufacturer Part Number: CC0603KRX7R9BB104
D8 D9 = SS210F: as D6 on sheet Power path switch
D10 D11 = 1N5819WS: Schottky 40V 1A 600mVf SOD-323; Manufacturer: Guangdong Hottech
D13-D15 = XL-1608UOC-06: as D2 on sheet USB protection
D16 = PSC-1608U52GC-G4: LED Green 0603 20mA; Manufacturer: HONGLITRONIC
IC5 = BQ25756RRVR: Charger IC; Manufacturer: Texas Instruments
L1 = SMMS1770-150M: Inductor 15uH 25Asat 13mR 30V; Manufacturer: SXN
NT1 = NetTie: Net Tie
Q6-Q9 = DON120N06: Nmos 60V 120A 3.5mR 1120pF DFN-8(5x6); Manufacturer: DOINGTER
R25 R26 = 0805W8F1000T5E: Res 100R 0805 1% 125mW 150V; Manufacturer: UNI-ROYAL
R27 = RLM25FEER005: Res 5mR 2512 1% 2W; Manufacturer: TA-I Tech
R28 = FRM121WFR005TM: Res 5mR 1206 1% 1W; Manufacturer: FOJAN
R29-R32 = 0603WAF100JT5E: Res 10R 0603 1% 100mW 75V; Manufacturer: Uni-Royal
R33-R38 = 0603WAF220KT5E: Res 2R2 0603 1% 100mW 75V; Manufacturer: Uni-Royal
R39 = RT0603BRD07249KL: Res 249K 0603 0.1% 100mW 75V; Manufacturer: YAGEO
R40 = FRC0603F7321TS: Res 7k32 0603 1% 100mW 75V; Manufacturer: Fojan
R41 = 0603WAF1004T5E: Res 1M 0603 1% 100mW 75V; Manufacturer: Uni-Royal
R42 = 0603WAF5101T5E: Res 5k1 0603 1% 100mW 75V; Manufacturer: Uni-Royal
R43 = 0603WAF3483T5E: Res 348k 0603 1% 100mW 75V; Manufacturer: Uni-Royal
R44 R45 = 0603WAF220JT5E: as R19 on sheet USB PD
R46 = 0603WAF6201T5E: Res 6k2 0603 1% 100mW 75V; Manufacturer: Uni-Royal
R47 R133 = 0603WAF3012T5E: Res 30k1 0603 1% 100mW 75V; Manufacturer: Uni-Royal
R49 = FRC0603F3741TS: Res 3K74 0603 1% 100mW 75V; Manufacturer: FOJAN
R50 = 0603WAF2003T5E: Res 200K 0603 1% 100mW 75V; Manufacturer: UNI-ROYAL
R51 R52 = 0603WAF4532T5E: Res 45k3 0603 1% 100mW 75V; Manufacturer: Uni-Royal
R53 R54 = 0603WAF1002T5E: as R3 on sheet USB protection
X13-X17 = ZX-PZ1.27-1-2PZZ: as X2 on sheet USB protection

## Sheet Power distribution.SchDoc
size A3; SheetNumber: 7; SheetTotal: 8
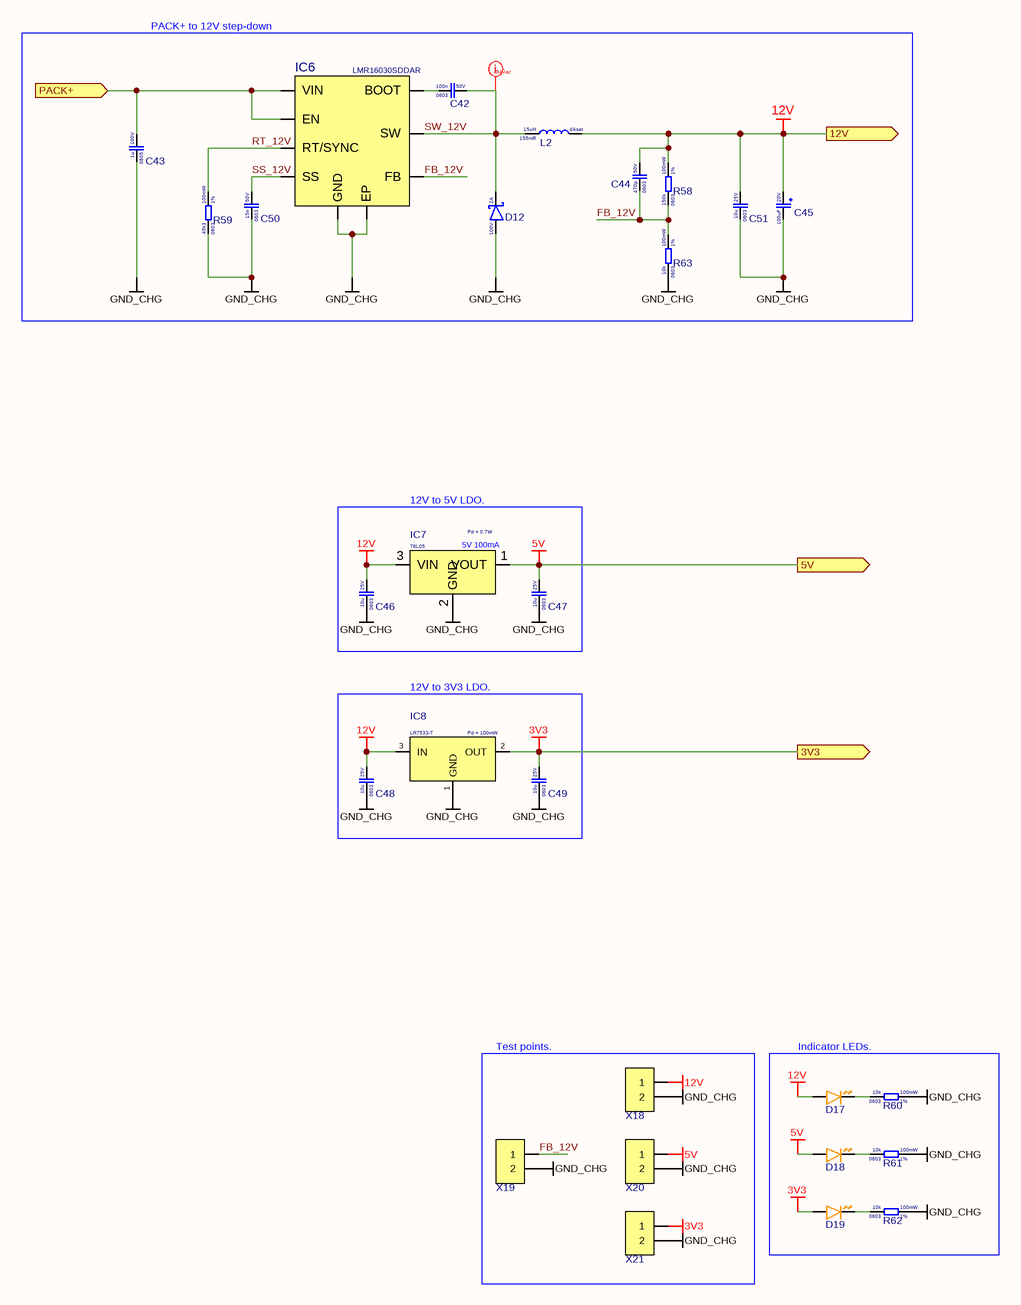
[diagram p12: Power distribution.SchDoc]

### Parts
C42  Voltage Rating: 50V  Case Code (Imperial): 0603  Capacitance: 100n  [CAP 0603]  (hidden comment: CC0603KRX7R9BB104)
C43  Voltage Rating: 100V  Case Code (Imperial): 0805  Capacitance: 1u  [Cap_0805]  (hidden comment: CC0805KKX7R0BB105)
C44  Voltage Rating: 50V  Case Code (Imperial): 0603  Capacitance: 470p  [CAP 0603]  (hidden comment: 0603B471K500NT)
C45  Voltage Rating: 20V  Capacitance: 100uF  [CASE D 7343-31]  (hidden comment: TAJD107K020RNJ)
C46  Voltage Rating: 25V  Case Code (Imperial): 0603  Capacitance: 10u  [CAP 0603]  (hidden comment: CL10A106MA8NRNC)
C47  Voltage Rating: 25V  Case Code (Imperial): 0603  Capacitance: 10u  [CAP 0603]  (hidden comment: CL10A106MA8NRNC)
C48  Voltage Rating: 25V  Case Code (Imperial): 0603  Capacitance: 10u  [CAP 0603]  (hidden comment: CL10A106MA8NRNC)
C49  Voltage Rating: 25V  Case Code (Imperial): 0603  Capacitance: 10u  [CAP 0603]  (hidden comment: CL10A106MA8NRNC)
C50  Voltage Rating: 50V  Case Code (Imperial): 0603  Capacitance: 15n  [CAP 0603]  (hidden comment: CC0603KRX7R9BB153)
C51  Voltage Rating: 25V  Case Code (Imperial): 0603  Capacitance: 10u  [CAP 0603]  (hidden comment: CL10A106MA8NRNC)
D12  Forward Current: 2A  Reverse Voltage: 100V  [SMAF]  (hidden comment: SS210F)
D17  XL-1608UOC-06  [DIODE_0603_ORANGE]  (value not drawn)
D18  XL-1608UOC-06  [DIODE_0603_ORANGE]  (value not drawn)
D19  XL-1608UOC-06  [DIODE_0603_ORANGE]  (value not drawn)
IC6  LMR16030SDDAR  [SOIC8-EP]
IC7  Pd = 0.7W  [SOT-89-3]
IC8  Pd = 100mW  [SOT-23 123]
L2  Resistance: 155mR  Saturation current: 4Asat  Inductance: 15uH  [FXL0630-150-M]  (hidden comment: FXL0630-150-M)
R58  Resistance Tolerance: 1%  Resistance: 150k  Power Rating: 100mW  Case Code (Imperial): 0603  [RES_0603]  (hidden comment: 0603WAF1503T5E)
R59  Resistance Tolerance: 1%  Resistance: 45k3  Power Rating: 100mW  Case Code (Imperial): 0603  [RES_0603]  (hidden comment: 0603WAF4532T5E)
R60  Resistance Tolerance: 1%  Resistance: 10k  Power Rating: 100mW  Case Code (Imperial): 0603  [RES_0603]  (hidden comment: 0603WAF1002T5E)
R61  Resistance Tolerance: 1%  Resistance: 10k  Power Rating: 100mW  Case Code (Imperial): 0603  [RES_0603]  (hidden comment: 0603WAF1002T5E)
R62  Resistance Tolerance: 1%  Resistance: 10k  Power Rating: 100mW  Case Code (Imperial): 0603  [RES_0603]  (hidden comment: 0603WAF1002T5E)
R63  Resistance Tolerance: 1%  Resistance: 10k  Power Rating: 100mW  Case Code (Imperial): 0603  [RES_0603]  (hidden comment: 0603WAF1002T5E)
X18  ZX-PZ1.27-1-2PZZ  [Pin header 1x2 1.27mmP THT Vertical]  (value not drawn)
X19  ZX-PZ1.27-1-2PZZ  [Pin header 1x2 1.27mmP THT Vertical]  (value not drawn)
X20  ZX-PZ1.27-1-2PZZ  [Pin header 1x2 1.27mmP THT Vertical]  (value not drawn)
X21  ZX-PZ1.27-1-2PZZ  [Pin header 1x2 1.27mmP THT Vertical]  (value not drawn)

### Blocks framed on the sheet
PACK+ to 12V step-down: C42-C45 C50 C51 D12 IC6 L2 R58 R59 R63
12V to 5V LDO.: C46 C47 IC7
12V to 3V3 LDO.: C48 C49 IC8
Test points.: X18-X21
Indicator LEDs.: D17-D19 R60-R62

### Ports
3V3 (out, see CHARGER[4C], USB PD[5B]), 5V (out, see CHARGER[4C], USB PD[2B]), 12V (out, see CHARGER[4C], Charger BQ25756[8A]), PACK+ (in, see CHARGER[3C], BMS[8A], Charger BQ25756[1A], CHARGER[1B])

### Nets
3V3: C49.2 D19.A IC8.2(OUT) X21.1 ; port 3V3
5V: C47.2 D18.A IC7.1(VOUT) X20.1 ; port 5V
12V: C44.2 C45.+ C46.2 C48.2 C51.2 D17.A IC7.3(VIN) IC8.3(IN) L2.2 R58.2 X18.1 ; port 12V
GND_CHG: C43.1 C45.- C46.1 C47.1 C48.1 C49.1 C50.1 C51.1 D12.A IC6.7(GND) IC6.9(EP) IC7.2(GND) IC8.1(GND) R59.1 R60.2 R61.2 R62.2 R63.1 X18.2 X19.2 X20.2 X21.2
FB_12V: C44.1 IC6.5(FB) R58.1 R63.2 X19.1
PACK+: C43.2 IC6.2(VIN) IC6.3(EN) ; port PACK+
RT_12V: IC6.4(RT/SYNC) R59.2
SS_12V: C50.2 IC6.6(SS)
SW_12V: C42.2 D12.K IC6.8(SW) L2.1
NetC42_1: C42.1 IC6.1(BOOT)
NetD17_K: D17.K R60.1
NetD18_K: D18.K R61.1
NetD19_K: D19.K R62.1

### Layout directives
net class 54Vac: SW_12V

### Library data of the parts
C42 = CC0603KRX7R9BB104: Cap 100nF 50V 0603 X7R; Manufacturer: Yageo
C43 = CC0805KKX7R0BB105: as C1 on sheet USB protection
C44 = 0603B471K500NT: Cap 470pF 50V 0603 X7R; Manufacturer: FH
C45 = TAJD107K020RNJ: Tantal cap 100uF 20V 500mR CASE D-7343-31; Manufacturer: Kyocera AVX
C46-C49 C51 = CL10A106MA8NRNC: as C5 on sheet USB protection
C50 = CC0603KRX7R9BB153: as C41 on sheet Charger BQ25756
D12 = SS210F: as D6 on sheet Power path switch
D17-D19 = XL-1608UOC-06: as D2 on sheet USB protection
IC6 = LMR16030SDDAR: Step-down 4.3~60Vin 3A SOIC8-EP 0.2~2.5MHz IntFET; Manufacturer: Texas Instruments
IC7 = 78L05: LDO 5V 100mA 30Vin; Manufacturer: UMW
IC8 = LR7533-T: LDO 24Vin 3.3Vout fixed; Manufacturer: LR
L2 = FXL0630-150-M: Inductor 15uH 3A 115mR 30V; Manufacturer: Cjiang
R58 = 0603WAF1503T5E: Res 150k 0603 1% 100mW 75V; Manufacturer: Uni-Royal
R59 = 0603WAF4532T5E: as R51 on sheet Charger BQ25756
R60-R63 = 0603WAF1002T5E: as R3 on sheet USB protection
X18-X21 = ZX-PZ1.27-1-2PZZ: as X2 on sheet USB protection

## Sheet ESD system side.SchDoc
size A3; SheetNumber: 14; SheetTotal: 15
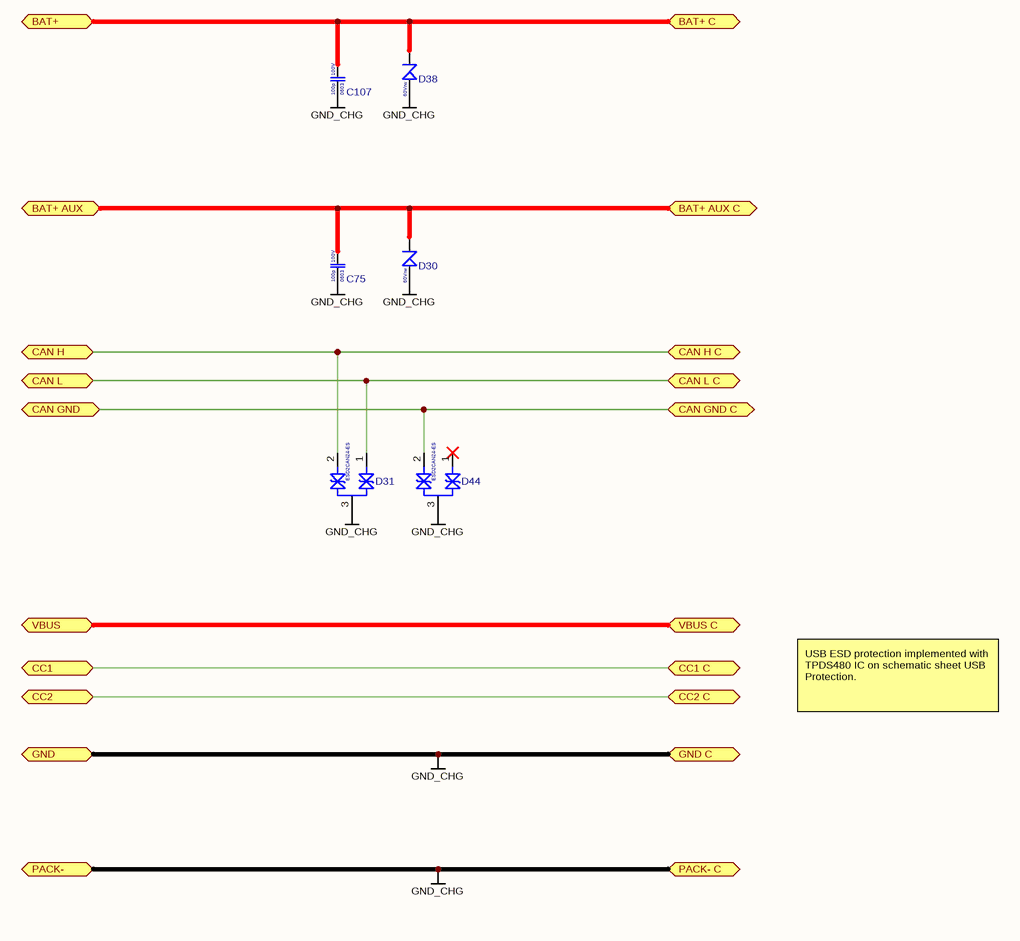
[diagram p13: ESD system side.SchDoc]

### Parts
C75  Voltage Rating: 100V  Case Code (Imperial): 0603  Capacitance: 100p  [CAP 0603]  (hidden comment: CC0603JRNPO0BN101)
C107  Voltage Rating: 100V  Case Code (Imperial): 0603  Capacitance: 100p  [CAP 0603]  (hidden comment: CC0603JRNPO0BN101)
D30  Reverse Voltage: 60Vrw  [DO-214AA]  (hidden comment: SMBJ60A)
D31  ESD2CAN24-ES  [SOT-23 123]
D38  Reverse Voltage: 60Vrw  [DO-214AA]  (hidden comment: SMBJ60A)
D44  ESD2CAN24-ES  [SOT-23 123]

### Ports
BAT+ (bidir, see Arhitecture[6A]), BAT+ AUX (bidir, see Arhitecture[6A]), BAT+ AUX C (bidir, see Arhitecture[7A]), BAT+ C (bidir, see Arhitecture[7A]), CAN GND (bidir, see Arhitecture[6B], BMS[8B], MCU[8B]), CAN GND C (bidir, see Arhitecture[7B]), CAN H (bidir, see Arhitecture[6B], BMS[8B], MCU[8A]), CAN H C (bidir, see Arhitecture[7B]), CAN L (bidir, see Arhitecture[6B], BMS[8B], MCU[8B]), CAN L C (bidir, see Arhitecture[7B]), CC1 (bidir, see Arhitecture[6B], CHARGER[8B]), CC1 C (bidir, see Arhitecture[7B]), CC2 (bidir, see Arhitecture[6C], CHARGER[8B]), CC2 C (bidir, see Arhitecture[7C]), GND (bidir, see Arhitecture[6C], CHARGER[8C]), GND C (bidir, see Arhitecture[7C]), PACK- (bidir, see Arhitecture[6D], BMS[8D], CHARGER[1C]), PACK- C (bidir, see Arhitecture[7D]), VBUS (bidir, see Arhitecture[6B], CHARGER[8A], Power path switch[5B], USB protection[5A]), VBUS C (bidir, see Arhitecture[7B])

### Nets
GND CAN: D44.2 ; port CAN GND, port CAN GND C
GND_CHG: C75.1 C107.1 D30.A D31.3 D38.A D44.3 ; port GND C, port GND, port PACK- C, port PACK-
C_CC1: port CC1 C, port CC1
C_CC2: port CC2 C, port CC2
CAN H: D31.2 ; port CAN H, port CAN H C
CAN L: D31.1 ; port CAN L, port CAN L C
VBUS: port VBUS C, port VBUS
NetC75_2: C75.2 D30.K ; port BAT+ AUX, port BAT+ AUX C
NetC107_2: C107.2 D38.K ; port BAT+ C, port BAT+

Not connected (* = marked no-connect by the designer): D44 1*

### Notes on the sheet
- USB ESD protection implemented with TPDS480 IC on schematic sheet USB Protection.

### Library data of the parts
C75 C107 = CC0603JRNPO0BN101: as C18 on sheet Charger BQ25756
D30 D38 = SMBJ60A: TVS ESD Zener UniD 60Vrw 1uA; Manufacturer: Shandong Jingdao Microelectronics
D31 D44 = ESD2CAN24-ES: ESD TVS CAN; Manufacturer: ElecSuper

## Sheet ESD battery side.SchDoc
size A3; SheetNumber: 15; SheetTotal: 15
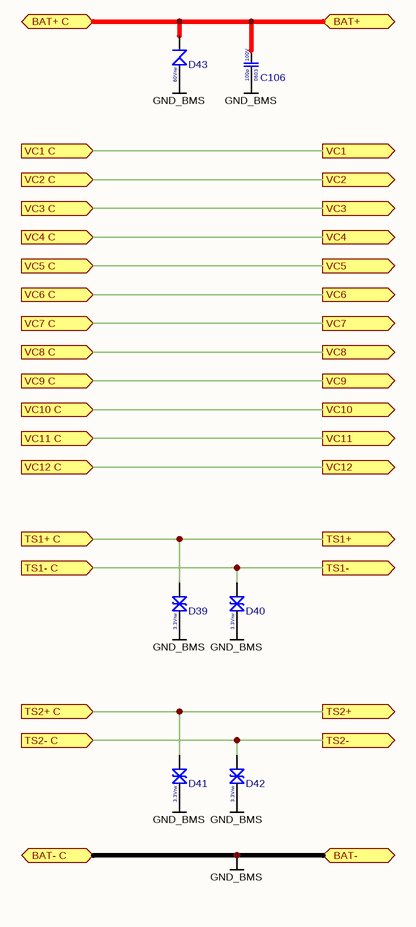
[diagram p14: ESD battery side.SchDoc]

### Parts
C106  Voltage Rating: 100V  Case Code (Imperial): 0603  Capacitance: 100p  [CAP 0603]  (hidden comment: CC0603JRNPO0BN101)
D39  V_RWM: 3.3Vrw  [SOD-523]  (hidden comment: H3V3LD5B)
D40  V_RWM: 3.3Vrw  [SOD-523]  (hidden comment: H3V3LD5B)
D41  V_RWM: 3.3Vrw  [SOD-523]  (hidden comment: H3V3LD5B)
D42  V_RWM: 3.3Vrw  [SOD-523]  (hidden comment: H3V3LD5B)
D43  Reverse Voltage: 60Vrw  [DO-214AA]  (hidden comment: SMBJ60A)

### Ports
BAT+ (bidir, see Arhitecture[2B], BAT+ to 5V1 STEP-DOWN[3B], BMS[1A], BQ34Z100 FUEL GAUGE[3A], BQ76952 BMS[1A]), BAT+ C (bidir, see Arhitecture[2B]), BAT- (bidir, see Arhitecture[2C], BMS[1D]), BAT- C (bidir, see Arhitecture[2C]), TS1+ (out, see Arhitecture[2B], Charger BQ25756[2C], CHARGER[1B]), TS1+ C (in, see Arhitecture[2B]), TS1- (out, see Arhitecture[2B], Charger BQ25756[2C], CHARGER[1B]), TS1- C (in, see Arhitecture[2B]), TS2+ (out, see Arhitecture[2C], BMS[1C], BQ76952 BMS[3C]), TS2+ C (in, see Arhitecture[2C]), TS2- (out, see Arhitecture[2C], BMS[1C], BQ76952 BMS[3C]), TS2- C (in, see Arhitecture[2C]), VC1 (out, see Arhitecture[2B], BMS[1B], BQ76952 BMS[1C]), VC1 C (in, see Arhitecture[2B]), VC2 (out, see Arhitecture[2B], BMS[1B], BQ76952 BMS[1C]), VC2 C (in, see Arhitecture[2B]), VC3 (out, see Arhitecture[2B], BMS[1B], BQ76952 BMS[1C]), VC3 C (in, see Arhitecture[2B]), VC4 (out, see Arhitecture[2B], BMS[1B], BQ76952 BMS[1C]), VC4 C (in, see Arhitecture[2B]), VC5 (out, see Arhitecture[2B], BMS[1B], BQ76952 BMS[1C]), VC5 C (in, see Arhitecture[2B]), VC6 (out, see Arhitecture[2B], BMS[1B], BQ76952 BMS[1C]), VC6 C (in, see Arhitecture[2B]), VC7 (out, see Arhitecture[2B], BMS[1B], BQ76952 BMS[1C]), VC7 C (in, see Arhitecture[2B]), VC8 (out, see Arhitecture[2B], BMS[1B], BQ76952 BMS[1B]), VC8 C (in, see Arhitecture[2B]), VC9 (out, see Arhitecture[2B], BMS[1B], BQ76952 BMS[1B]), VC9 C (in, see Arhitecture[2B]), VC10 (out, see Arhitecture[2B], BMS[1B], BQ76952 BMS[1B]), VC10 C (in, see Arhitecture[2B]), VC11 (out, see Arhitecture[2B], BMS[1B], BQ76952 BMS[1B]), VC11 C (in, see Arhitecture[2B]), VC12 (out, see Arhitecture[2B], BMS[1B], BQ76952 BMS[1B]), VC12 C (in, see Arhitecture[2B])

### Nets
GND_BMS: C106.1 D39.K D40.K D41.K D42.A D42.K D43.A ; port TS2- C, port TS2-, port BAT- C, port BAT-
BAT+: C106.2 D43.K ; port BAT+ C, port BAT+
TS: D39.A ; port TS1+ C, port TS1+
NetC83_2: D41.A ; port TS2+ C, port TS2+
NetD40_A: D40.A ; port TS1- C, port TS1-
NetR65_1: port VC12 C, port VC12
NetR66_1: port VC11 C, port VC11
NetR67_1: port VC10 C, port VC10
NetR68_1: port VC9 C, port VC9
NetR69_1: port VC8 C, port VC8
NetR70_1: port VC7 C, port VC7
NetR71_1: port VC6 C, port VC6
NetR72_1: port VC5 C, port VC5
NetR73_1: port VC4 C, port VC4
NetR74_1: port VC3 C, port VC3
NetR75_1: port VC2 C, port VC2
NetR76_1: port VC1 C, port VC1

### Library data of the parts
C106 = CC0603JRNPO0BN101: as C18 on sheet Charger BQ25756
D39-D42 = H3V3LD5B: ESD TVS 3.3Vrw 0.2uA 12.5pF; Manufacturer: hongjiacheng
D43 = SMBJ60A: as D30 on sheet ESD system side

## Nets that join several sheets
3V3: USB PD (C9.2 IC2.32), Power distribution (C49.2 D19.A IC8.2 X21.1)
5V: USB PD (C7.2 IC2.28 IC2.29), Power distribution (C47.2 D18.A IC7.1 X20.1)
5V BMS: BMS (D4.K), MCU (C90.2 IC11.3 R104.1), BAT+ to 5V1 STEP-DOWN (5 pins), 5V to 3V3 LDO (C99.2 IC14.2)
12V: Charger BQ25756 (D10.A), Power distribution (11 pins)
GND CAN: Arhitecture (X24.3), MCU (11 pins), ESD system side (D44.2)
GND_BMS: Arhitecture (17 pins), BMS (R78.1), BQ76952 BMS (19 pins), BQ34Z100 FUEL GAUGE (12 pins), MCU (30 pins), BAT+ to 5V1 STEP-DOWN (6 pins), 5V to 3V3 LDO (5 pins), ESD battery side (7 pins)
GND_CHG: Arhitecture (14 pins), BMS (R78.2), BQ76952 BMS (D22.A R80.1), BQ34Z100 FUEL GAUGE (R128.1), USB protection (16 pins), USB PD (39 pins), Power path switch (5 pins), Charger BQ25756 (40 pins), Power distribution (22 pins), ESD system side (6 pins)
LDO_3V3: USB protection (C5.2 IC1.10 R3.2), USB PD (16 pins)
VDD: Arhitecture (X22.1), BQ34Z100 FUEL GAUGE (C101.2 IC15.5 IC15.6), MCU (7 pins), 5V to 3V3 LDO (C100.2 IC14.3)
BAT+: Arhitecture (F1.1 F2.1 X30.1), BQ76952 BMS (7 pins), BQ34Z100 FUEL GAUGE (Q15.S R129.2), BAT+ to 5V1 STEP-DOWN (D37.A), ESD battery side (C106.2 D43.K)
C_CC1: Arhitecture (X25.A5), USB protection (IC1.4 R1.1)
C_CC2: Arhitecture (X25.B5), USB protection (IC1.5 R2.1)
CAN H: Arhitecture (X24.1), MCU (L3.4), ESD system side (D31.2)
CAN L: Arhitecture (X24.2), MCU (L3.3), ESD system side (D31.1)
CC1: USB protection (IC1.12), USB PD (C11.2 IC2.24 X8.1)
CC2: USB protection (IC1.11), USB PD (C10.2 IC2.25 X11.1)
ERP_EN: USB protection (IC1.16 X4.1), USB PD (IC2.7)
NetC75_2: Arhitecture (F2.2), ESD system side (C75.2 D30.K)
NetC83_2: Arhitecture (X31.15), BQ76952 BMS (C83.2 IC9.21), ESD battery side (D41.A)
NetC107_2: Arhitecture (F1.2 X26.1 X26.2), ESD system side (C107.2 D38.K)
NetD40_A: Arhitecture (X31.14), Charger BQ25756 (NT1.1), ESD battery side (D40.A)
NetD49_K: Arhitecture (D49.K X22.2), MCU (R106.2)
NetD50_K: Arhitecture (D50.K X22.4), MCU (R107.2)
NetIC9_29: BQ76952 BMS (IC9.29), MCU (IC10.19)
NetIC9_30: BQ76952 BMS (IC9.30), MCU (IC10.18)
NetIC10_16: BQ76952 BMS (R100.2), MCU (IC10.16)
NetIC10_17: BQ76952 BMS (R101.2), MCU (IC10.17)
NetIC13_3: MCU (R119.1), BAT+ to 5V1 STEP-DOWN (IC13.3)
NetR65_1: Arhitecture (X31.12), BQ76952 BMS (R65.1)
NetR66_1: Arhitecture (X31.11), BQ76952 BMS (R66.1)
NetR67_1: Arhitecture (X31.10), BQ76952 BMS (R67.1)
NetR68_1: Arhitecture (X31.9), BQ76952 BMS (R68.1)
NetR69_1: Arhitecture (X31.8), BQ76952 BMS (R69.1)
NetR70_1: Arhitecture (X31.7), BQ76952 BMS (R70.1)
NetR71_1: Arhitecture (X31.6), BQ76952 BMS (R71.1)
NetR72_1: Arhitecture (X31.5), BQ76952 BMS (R72.1)
NetR73_1: Arhitecture (X31.4), BQ76952 BMS (R73.1)
NetR74_1: Arhitecture (X31.3), BQ76952 BMS (R74.1)
NetR75_1: Arhitecture (X31.2), BQ76952 BMS (R75.1)
NetR76_1: Arhitecture (X31.1), BQ76952 BMS (R76.1)
nRST: Arhitecture (D51.K X22.10), MCU (C89.2 IC10.4 R108.1)
PACK+: BQ76952 BMS (9 pins), Charger BQ25756 (7 pins), Power distribution (C43.2 IC6.2 IC6.3)
PP_EN: USB PD (Q2.D R6.1 X12.1), Power path switch (IC4.1)
REG1: BMS (D4.A), BQ76952 BMS (C81.2 IC9.35)
SCL: Arhitecture (D46.K X29.2), USB PD (R8.1 R18.2 R20.2 X10.1), Charger BQ25756 (R44.2)
SCLt: Arhitecture (D48.K X28.2), BQ76952 BMS (R97.2), BQ34Z100 FUEL GAUGE (R126.2), MCU (R98.1 R110.1), USB PD (R48.1 R57.2)
SDA: Arhitecture (D45.K X29.1), USB PD (5 pins), Charger BQ25756 (R45.2)
SDAt: Arhitecture (D47.K X28.1), BQ76952 BMS (R96.2), BQ34Z100 FUEL GAUGE (R125.2), MCU (R99.1 R111.1), USB PD (R55.1 R56.2)
TS: Arhitecture (X31.13), Charger BQ25756 (5 pins), ESD battery side (D39.A)
V_CHG_IN: Power path switch (C15.2 D6.A Q4.D), Charger BQ25756 (9 pins)
VBUS: Arhitecture (X25.A4_B9 X25.B4_A9), USB protection (7 pins), Power path switch (C16.2 D7.A Q5.D)
VBUS_LV: USB protection (5 pins), USB PD (C8.2 IC2.26 IC2.27)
